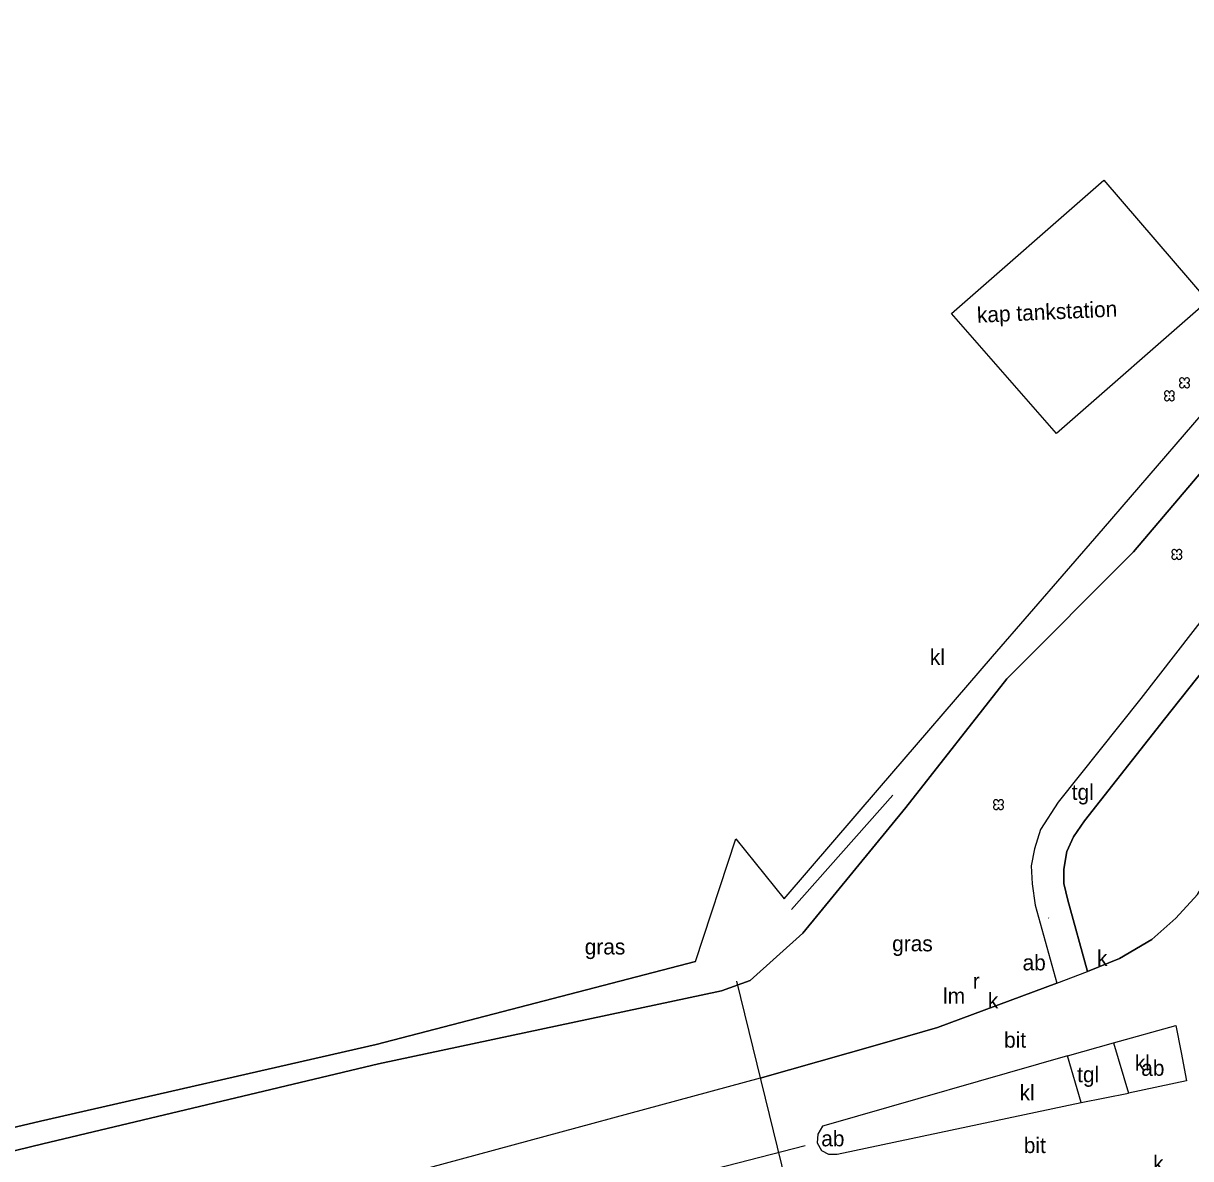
# Model space of a CAD drawing. Extents: x 154825 to 158680, y 370717 to 378075.
# Drawn here: x 156800 to 156874.8, y 372483.5 to 372556.2 of the extents above; entities that cross this region are included whole.
import ezdxf

# ---------------------------------------------------------------- set-up
doc = ezdxf.new("R2010")
doc.units = 0
for name, color, linetype in [('ab zonder kabel', 7, 'Continuous'), ('bitumenverharding(vs)', 7, 'Continuous'), ('boom', 7, 'Continuous'), ('breuklijn', 7, 'Continuous'), ('duiker lijn', 7, 'Continuous'), ('grazige vegetatie(vs)', 7, 'Continuous'), ('greppel - midden sloot', 7, 'Continuous'), ('klinkerverharding(vs)', 7, 'Continuous'), ('kolk', 7, 'Continuous'), ('maaiveldlijn algemeen - gesloten verharding', 7, 'Continuous'), ('maaiveldlijn algemeen - muur', 7, 'Continuous'), ('maaiveldlijn algemeen - verharding algemeen', 7, 'Continuous'), ('ondefinieerbaar(vs)', 7, 'Continuous'), ('raster - hek', 7, 'Continuous'), ('rioolput(z_inl)', 7, 'Continuous'), ('talud(boven)', 7, 'Continuous'), ('talud(onder)', 7, 'Continuous'), ('tegelverh(vs)', 7, 'Continuous'), ('verlichtingsobject', 7, 'Continuous'), ('vlak_Grazige_vegetatie', 7, 'Continuous')]:
    doc.layers.add(name, color=color, linetype=linetype)

msp = doc.modelspace()

# ---------------------------------------------------------------- linework, layer by layer
at = {"layer": 'boom'}
for centre in [(156874.373, 372533.189), (156873.405, 372532.353), (156873.879, 372522.199), (156862.452, 372506.171)]:
    msp.add_circle(centre, 0.006, dxfattribs=at)
for centre, start, end in [((156874.215, 372533.347), 357.07502, 272.92498), ((156874.531, 372533.347), 267.07502, 182.92498), ((156874.215, 372533.031), 87.07502, 2.92498), ((156874.531, 372533.031), 177.07502, 92.92498), ((156873.247, 372532.511), 357.07502, 272.92498), ((156873.247, 372532.195), 87.07502, 2.92498), ((156873.563, 372532.511), 267.07502, 182.92498), ((156873.563, 372532.195), 177.07502, 92.92498), ((156873.721, 372522.357), 357.07502, 272.92498), ((156874.037, 372522.357), 267.07502, 182.92498), ((156873.721, 372522.041), 87.07502, 2.92498), ((156874.037, 372522.041), 177.07502, 92.92498), ((156862.294, 372506.33), 357.07502, 272.92498), ((156862.294, 372506.013), 87.07502, 2.92498), ((156862.61, 372506.33), 267.07502, 182.92498), ((156862.61, 372506.013), 177.07502, 92.92498)]:
    msp.add_arc(centre, 0.158, start, end, dxfattribs=at)
at = {"layer": 'breuklijn'}
for points in [[(156846.549, 372494.899), (156849.905, 372497.933), (156856.513, 372505.993), (156862.994, 372514.234), (156871.098, 372522.372), (156877.833, 372530.284), (156879.967, 372533.054), (156889.984, 372544.53), (156897.461, 372553.778), (156899.668, 372556.213)], [(156865.686, 372498.906), (156865.656, 372498.915)], [(156850.054, 372484.313), (156836.378, 372480.807), (156817.278, 372476.145), (156790.368, 372469.929), (156779.039, 372467.266), (156757.337, 372462.37), (156736.041, 372457.495), (156708.382, 372450.808), (156659.715, 372438.872)]]:
    msp.add_lwpolyline(points, dxfattribs=at)
at = {"layer": 'duiker lijn'}
msp.add_lwpolyline([(156845.659, 372494.869), (156851.156, 372472.474)], dxfattribs=at)
at = {"layer": 'greppel - midden sloot'}
msp.add_lwpolyline([(156849.198, 372499.452), (156855.672, 372506.771)], dxfattribs=at)
at = {"layer": 'maaiveldlijn algemeen - gesloten verharding'}
for points in [[(156868.148, 372495.483), (156870.212, 372496.312), (156872.281, 372497.541), (156873.82, 372498.894), (156875.205, 372500.42), (156875.953, 372501.678), (156877.151, 372503.946), (156878.25, 372505.823), (156879.449, 372507.359), (156880.966, 372508.985), (156882.621, 372510.382), (156884.434, 372511.634), (156886.05, 372512.766), (156887.195, 372514.05), (156888.402, 372515.9), (156888.98, 372517.192), (156889.965, 372520.122)], [(156866.184, 372494.747), (156868.148, 372495.483)], [(156847.185, 372488.652), (156854.691, 372490.798), (156858.543, 372491.906), (156866.184, 372494.747)], [(156869.829, 372490.912), (156873.828, 372492.032), (156874.167, 372490.293), (156874.51, 372488.481), (156870.779, 372487.692)], [(156866.87, 372490.075), (156869.829, 372490.912)], [(156866.87, 372490.075), (156851.557, 372485.694), (156851.173, 372485.57), (156850.876, 372485.077), (156850.825, 372484.505), (156851.107, 372484.016), (156851.55, 372483.778), (156852.109, 372483.778), (156867.751, 372487.095)], [(156847.185, 372488.652), (156806.812, 372477.717), (156790.28, 372473.561), (156778.386, 372470.925), (156756.776, 372466.021), (156736.523, 372461.681), (156736.662, 372461.207), (156710.821, 372455.118), (156688.091, 372449.534), (156688.016, 372449.78)], [(156847.185, 372488.652), (156848.53, 372489.037)], [(156867.751, 372487.095), (156870.779, 372487.692)]]:
    msp.add_lwpolyline(points, dxfattribs=at)
at = {"layer": 'maaiveldlijn algemeen - muur'}
msp.add_lwpolyline([(156875.934, 372538.489), (156866.16, 372529.936), (156859.434, 372537.622), (156869.208, 372546.175), (156875.865, 372538.428)], dxfattribs=at)
at = {"layer": 'maaiveldlijn algemeen - verharding algemeen'}
for points in [[(156899.173, 372548.379), (156893.944, 372541.673), (156878.09, 372521.354), (156871.567, 372512.962), (156866.271, 372506.339), (156865.149, 372504.579), (156864.759, 372503.351), (156864.546, 372502.256), (156864.61, 372501.094), (156864.796, 372499.727), (156866.184, 372494.747)], [(156889.965, 372520.122), (156881.608, 372520.637), (156880.841, 372520.593), (156880.328, 372520.393), (156879.248, 372519.393), (156873.102, 372511.642), (156867.969, 372505.126), (156867.261, 372504.105), (156866.831, 372503.169), (156866.636, 372502.044), (156866.636, 372501.116), (156866.896, 372500.065), (156868.148, 372495.483)], [(156869.829, 372490.912), (156870.779, 372487.692)], [(156867.751, 372487.095), (156866.87, 372490.075)]]:
    msp.add_lwpolyline(points, dxfattribs=at)
at = {"layer": 'raster - hek'}
msp.add_lwpolyline([(156845.629, 372503.985), (156848.71, 372500.143), (156854.823, 372507.239), (156862.068, 372515.653), (156869.178, 372523.863), (156876.112, 372531.891), (156878.026, 372534.012), (156885.775, 372542.945), (156885.152, 372543.495)], dxfattribs=at)
at = {"layer": 'talud(boven)'}
msp.add_lwpolyline([(156846.549, 372494.899), (156844.696, 372494.252), (156822.718, 372489.577), (156801.215, 372484.458), (156778.491, 372478.916), (156757.376, 372473.961), (156735.74, 372468.611), (156718.656, 372464.364), (156701.426, 372460.09), (156657.915, 372449.382)], dxfattribs=at)
at = {"layer": 'talud(onder)'}
msp.add_lwpolyline([(156843.034, 372496.131), (156822.565, 372490.82), (156801.058, 372485.904), (156778.493, 372480.594), (156757.319, 372475.643), (156735.668, 372470.544), (156717.951, 372466.262), (156700.779, 372462.073), (156692.083, 372460.01), (156681.289, 372457.629), (156672.605, 372455.292), (156663.734, 372453.435), (156653.129, 372450.865), (156643.464, 372448.392), (156631.541, 372445.759), (156624.449, 372444.04), (156614.182, 372441.532), (156593.972, 372436.822), (156569.385, 372431.109), (156542.246, 372423.792), (156539.497, 372424.201)], dxfattribs=at)
at = {"layer": 'vlak_Grazige_vegetatie'}
for points in [[(156778.492, 372480.593), (156801.058, 372485.904), (156822.565, 372490.82), (156843.034, 372496.131), (156845.629, 372503.985), (156848.709, 372500.143), (156854.823, 372507.239), (156862.068, 372515.653), (156869.178, 372523.863), (156876.112, 372531.891)], [(156778.491, 372478.916), (156801.215, 372484.458), (156822.718, 372489.577), (156844.696, 372494.252), (156846.549, 372494.899), (156849.905, 372497.933), (156856.513, 372505.993), (156862.994, 372514.234), (156871.098, 372522.372), (156877.833, 372530.284)], [(156877.833, 372530.284), (156871.098, 372522.372), (156862.994, 372514.234), (156856.513, 372505.993), (156849.905, 372497.933), (156846.549, 372494.899), (156844.696, 372494.252), (156822.718, 372489.577), (156801.215, 372484.458), (156778.491, 372478.916)], [(156878.09, 372521.354), (156871.567, 372512.962), (156866.271, 372506.339), (156865.149, 372504.579), (156864.759, 372503.351), (156864.546, 372502.256), (156864.61, 372501.094), (156864.796, 372499.727), (156866.184, 372494.747), (156858.543, 372491.906), (156854.691, 372490.798), (156847.185, 372488.652), (156806.812, 372477.717)], [(156875.205, 372500.42), (156873.82, 372498.894), (156872.281, 372497.541), (156870.212, 372496.312), (156868.148, 372495.483), (156866.896, 372500.065), (156866.636, 372501.116), (156866.636, 372502.044), (156866.831, 372503.169), (156867.261, 372504.105), (156867.969, 372505.126), (156873.102, 372511.642), (156879.248, 372519.393)]]:
    msp.add_lwpolyline(points, dxfattribs=at)

# ---------------------------------------------------------------- texts
at = {"layer": 'ab zonder kabel'}
for p in [(156863.996, 372495.557), (156871.601, 372488.804), (156851.094, 372484.287)]:
    msp.add_text('ab', height=1, dxfattribs=at).set_placement(p)
at = {"layer": 'bitumenverharding(vs)'}
for p in [(156862.811, 372490.606), (156864.076, 372483.857)]:
    msp.add_text('bit', height=1, dxfattribs=at).set_placement(p)
at = {"layer": 'grazige vegetatie(vs)'}
for p in [(156855.639, 372496.778), (156835.937, 372496.575)]:
    msp.add_text('gras', height=1, dxfattribs=at).set_placement(p)
at = {"layer": 'klinkerverharding(vs)'}
for p in [(156858.056, 372515.123), (156871.188, 372489.13), (156863.806, 372487.231)]:
    msp.add_text('kl', height=1, dxfattribs=at).set_placement(p)
at = {"layer": 'kolk'}
for p in [(156868.765, 372495.844), (156861.771, 372493.125), (156872.363, 372482.694)]:
    msp.add_text('k', height=1, dxfattribs=at).set_placement(p)
at = {"layer": 'ondefinieerbaar(vs)'}
msp.add_text('kap tankstation', height=1, rotation=2.60256, dxfattribs=at).set_placement((156861.095, 372537.034))
at = {"layer": 'rioolput(z_inl)'}
msp.add_text('r', height=1, dxfattribs=at).set_placement((156860.804, 372494.376))
at = {"layer": 'tegelverh(vs)'}
for p in [(156867.146, 372506.478), (156867.494, 372488.391)]:
    msp.add_text('tgl', height=1, dxfattribs=at).set_placement(p)
at = {"layer": 'verlichtingsobject'}
msp.add_text('lm', height=1, dxfattribs=at).set_placement((156858.902, 372493.426))

doc.saveas('drawing.dxf')
